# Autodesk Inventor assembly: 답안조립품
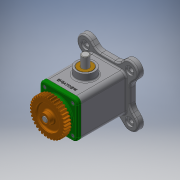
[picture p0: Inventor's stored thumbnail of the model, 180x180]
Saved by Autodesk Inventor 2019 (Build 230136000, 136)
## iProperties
Created: 2021-01
Part Number: 답안조립품
Material: 일반
Document SubType Name: Assembly
Designer: 3dpro8
Author: 3dpro8
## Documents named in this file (11)
- C:\Users\3dpro8\Desktop\710114V1010\답안조립품.iam
- C:\Users\3dpro8\Desktop\710114V1010\본체.ipt
- C:\Users\3dpro8\Desktop\710114V1010\베어링 6203.ipt
- C:\Users\3dpro8\Desktop\710114V1010\볼트 M4.ipt
- C:\Users\3dpro8\Desktop\710114V1010\부시.ipt
- C:\Users\3dpro8\Desktop\710114V1010\스퍼기어.ipt
- C:\Users\3dpro8\Desktop\710114V1010\슬라이더.ipt
- C:\Users\3dpro8\Desktop\710114V1010\오일 실.ipt
- C:\Users\3dpro8\Desktop\710114V1010\커버.ipt
- C:\Users\3dpro8\Desktop\710114V1010\키 4 x 4 x 14.ipt
- C:\Users\3dpro8\Desktop\710114V1010\편심축.ipt
